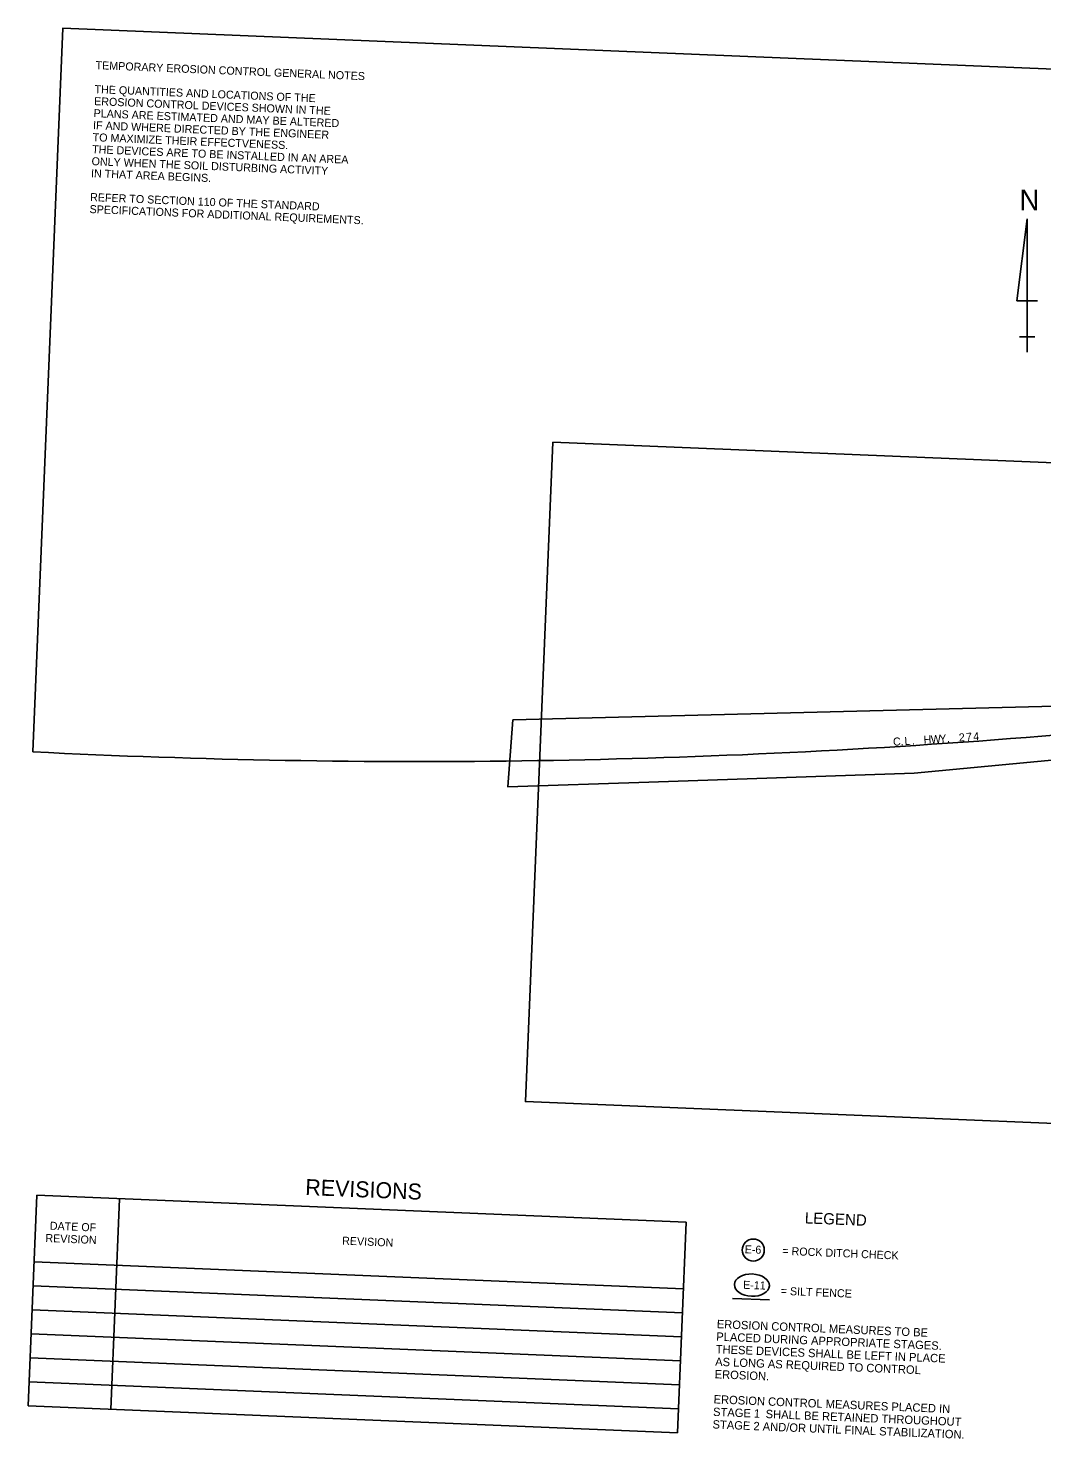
# Model space of a CAD drawing. Extents: x 1141845 to 1143465, y 1657054 to 1658153.
# Drawn here: x 1141845 to 1142605, y 1657096 to 1658153 of the extents above; entities that cross this region are included whole.
import ezdxf

# ---------------------------------------------------------------- set-up
doc = ezdxf.new("R2010")
doc.units = 0
for name, color, linetype in [('22', 7, 'Continuous'), ('R_Contour Annot', 7, 'Continuous'), ('R_Erosion_STG 2', 7, 'Continuous'), ('R_Proposed Const Limits_Fill', 7, 'Continuous')]:
    doc.layers.add(name, color=color, linetype=linetype)

msp = doc.modelspace()

# ---------------------------------------------------------------- linework, layer by layer
at = {"layer": '22'}
for p, q in [((1142593.7, 1658010.2), (1142586, 1657948.6)), ((1142593.7, 1657910.2), (1142593.7, 1658010.2)), ((1142593.7, 1658010.2), (1142593.7, 1657933.3)), ((1142586, 1657948.6), (1142601.4, 1657948.6)), ((1142593.7, 1657910.2), (1142593.7, 1657933.3)), ((1142593.7, 1657921.7), (1142587.9, 1657921.7)), ((1142587.9, 1657921.7), (1142599.4, 1657921.7)), ((1142593.7, 1657910.2), (1142593.7, 1657921.7))]:
    msp.add_line(p, q, dxfattribs=at)
at = {"layer": 'R_Contour Annot'}
for p, q in [((1141851.9, 1657278.2), (1141845.3, 1657120.3)), ((1141851.9, 1657278.2), (1142338.3, 1657258)), ((1141913.6, 1657275.6), (1141907.1, 1657117.7)), ((1142338.3, 1657258), (1142331.7, 1657100.2)), ((1141849.8, 1657228.2), (1142336.2, 1657208.1)), ((1141849.1, 1657210.2), (1142335.4, 1657190.1)), ((1141848.3, 1657192.2), (1142334.7, 1657172.1)), ((1141847.6, 1657174.2), (1142334, 1657154.1)), ((1141846.8, 1657156.3), (1142333.2, 1657136.1)), ((1141846.1, 1657138.3), (1142332.5, 1657118.2)), ((1141845.3, 1657120.3), (1142331.7, 1657100.2))]:
    msp.add_line(p, q, dxfattribs=at)
at = {"layer": 'R_Erosion_STG 2'}
msp.add_line((1142604.7, 1657622.4), (1143448.8, 1657691.4), dxfattribs=at)
msp.add_lwpolyline([(1143448.8, 1657691.4), (1143465.2, 1658087.1), (1141871.2, 1658153), (1141848.7, 1657610.6)], dxfattribs=at)
for points in [[(1142238.3, 1657842.8), (1142947.4, 1657813.5), (1142926.9, 1657319.1), (1142217.8, 1657348.4)], [(1142208.4, 1657634.5), (1142634.4, 1657645.3), (1142687.4, 1657659.4), (1142816.6, 1657654.9), (1142819.1, 1657625), (1142638.4, 1657606.8), (1142509, 1657594.5), (1142310.3, 1657587.8), (1142204.7, 1657584.3)]]:
    msp.add_lwpolyline(points, close=True, dxfattribs=at)
msp.add_arc((1142137.7, 1663333), 5729.7, 267.10951, 274.675, dxfattribs=at)
at = {"layer": 'R_Proposed Const Limits_Fill'}
msp.add_lwpolyline([(1142373, 1657200.9), (1142400.8, 1657199.8)], dxfattribs=at)
msp.add_circle((1142388.5, 1657237.1), 8.26, dxfattribs=at)
msp.add_ellipse((1142387.5, 1657210.8), major_axis=(13.1, -0.5), ratio=0.638788, dxfattribs=at)

# ---------------------------------------------------------------- texts
at = {"layer": '22'}
for s, height, rotation, p in [('TEMPORARY EROSION CONTROL GENERAL NOTES', 6, 357.6311, (1141895.7, 1658122.4)), ('THE QUANTITIES AND LOCATIONS OF THE', 6, 357.6311, (1141894.9, 1658104.4)), ('EROSION CONTROL DEVICES SHOWN IN THE ', 6, 357.6311, (1141894.6, 1658095.4)), ('PLANS ARE ESTIMATED AND MAY BE ALTERED ', 6, 357.6311, (1141894.2, 1658086.4)), ('TO MAXIMIZE THEIR EFFECTVENESS. ', 6, 357.6311, (1141893.5, 1658068.4)), ('IF AND WHERE DIRECTED BY THE ENGINEER ', 6, 357.6311, (1141893.8, 1658077.4)), ('THE DEVICES ARE TO BE INSTALLED IN AN AREA ', 6, 357.6311, (1141893.1, 1658059.4)), ('ONLY WHEN THE SOIL DISTURBING ACTIVITY', 6, 357.6311, (1141892.7, 1658050.4)), ('IN THAT AREA BEGINS.', 6, 357.6311, (1141892.3, 1658041.4)), ('N', 15.4, 360, (1142588, 1658016.6)), ('REFER TO SECTION 110 OF THE STANDARD ', 6, 357.6311, (1141891.6, 1658023.5)), ('SPECIFICATIONS FOR ADDITIONAL REQUIREMENTS.', 6, 357.6311, (1141891.2, 1658014.5)), ('C', 6, 3.7824, (1142493.4, 1657615.1)), ('L', 6, 3.7824, (1142502, 1657615.6)), ('H', 6, 3.7824, (1142516.3, 1657616.6)), ('W', 6, 3.7824, (1142521.7, 1657616.9)), ('Y', 6, 3.7824, (1142528.1, 1657617.4)), ('2', 6, 3.7824, (1142542.7, 1657618.3)), ('7', 6, 3.7824, (1142548.1, 1657618.7)), ('4', 6, 3.7824, (1142553.5, 1657619)), ('.', 6, 3.7824, (1142499.1, 1657615.4)), ('.', 6, 3.7824, (1142507.4, 1657616)), ('.', 6, 3.7824, (1142533.8, 1657617.7)), ('= ROCK DITCH CHECK', 6, 357.6311, (1142410.2, 1657233.6)), ('= SILT FENCE', 6, 357.6311, (1142409, 1657203.6)), ('PLACED DURING APPROPRIATE STAGES. ', 6.25, 357.6311, (1142360.7, 1657169.2)), ('EROSION CONTROL MEASURES TO BE', 6.25, 357.6311, (1142361.1, 1657178.6)), ('THESE DEVICES SHALL BE LEFT IN PLACE ', 6.25, 357.6311, (1142360.3, 1657159.8)), ('AS LONG AS REQUIRED TO CONTROL ', 6.25, 357.6311, (1142359.9, 1657150.4)), ('EROSION.', 6.25, 357.6311, (1142359.5, 1657141)), ('EROSION CONTROL MEASURES PLACED IN ', 6.25, 357.6311, (1142358.7, 1657122.2)), ('STAGE 1 ', 6.25, 357.6311, (1142358.3, 1657112.8)), ('SHALL BE RETAINED THROUGHOUT ', 6.25, 357.6311, (1142397.7, 1657111.2)), ('STAGE 2 AND/OR UNTIL FINAL STABILIZATION.', 6.25, 357.6311, (1142357.9, 1657103.4))]:
    msp.add_text(s, height=height, rotation=rotation, dxfattribs=at).set_placement(p)
at = {"layer": 'R_Contour Annot'}
for s, height, p in [('REVISIONS', 12, (1142052.7, 1657278.4)), ('REVISION', 6, (1141858.1, 1657243.2)), ('DATE OF', 6, (1141861.4, 1657252.4)), ('REVISION', 6, (1142080.4, 1657241.2))]:
    msp.add_text(s, height=height, rotation=357.6311, dxfattribs=at).set_placement(p)
at = {"layer": 'R_Proposed Const Limits_Fill'}
for s, height, rotation, p in [('LEGEND', 8.44, 357.6311, (1142427, 1657257.1)), ('E-6 ', 6, 358.0317, (1142382, 1657234.7)), ('E-11', 6, 357.8455, (1142380.8, 1657208.1))]:
    msp.add_text(s, height=height, rotation=rotation, dxfattribs=at).set_placement(p)

doc.saveas('drawing.dxf')
